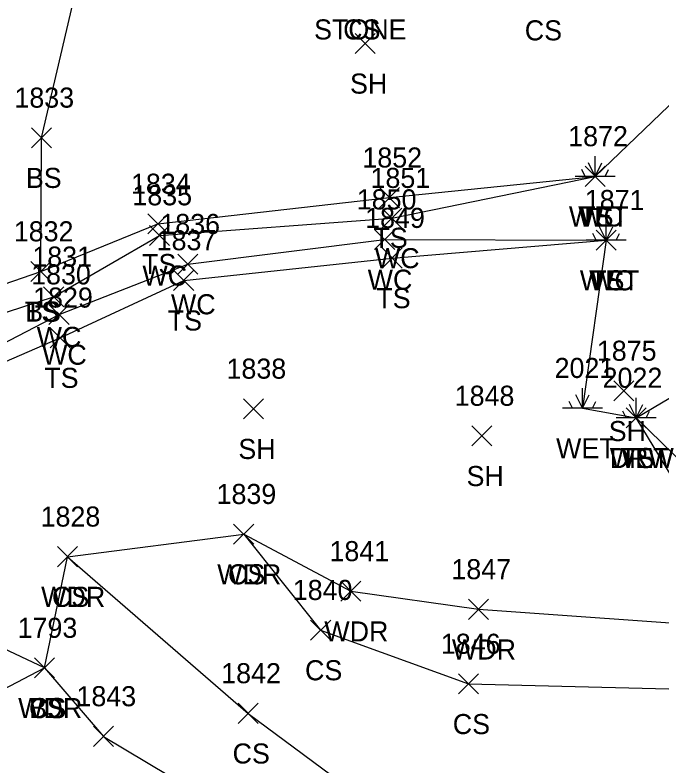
# Model space of a CAD drawing. Extents: x 1512665 to 1513714, y 110636 to 112816.
# Drawn here: x 1512769.8 to 1512834.1, y 110915.7 to 110990.4 of the extents above; entities that cross this region are included whole.
import ezdxf

# ---------------------------------------------------------------- set-up
doc = ezdxf.new("R2010")
doc.units = 0
for name, color, linetype in [('L_A', 7, 'Continuous'), ('L_I', 7, 'Continuous'), ('L_TIC', 7, 'Continuous'), ('LAWA', 7, 'Continuous'), ('LAWE', 7, 'Continuous'), ('LELB', 7, 'Continuous'), ('LWET', 7, 'Continuous'), ('R_A', 7, 'Continuous'), ('R_I', 7, 'Continuous'), ('R_TIC', 7, 'Continuous'), ('RDW', 7, 'Continuous')]:
    doc.layers.add(name, color=color, linetype=linetype)

msp = doc.modelspace()

# ---------------------------------------------------------------- linework, layer by layer
at = {"layer": 'L_TIC'}
for points in [[(1512803.661, 110986.564), (1512805.661, 110988.564)], [(1512805.661, 110986.564), (1512803.661, 110988.564)], [(1512771.399, 110977.169), (1512773.399, 110979.169)], [(1512773.399, 110977.169), (1512771.399, 110979.169)], [(1512826.592, 110973.325), (1512828.592, 110975.325)], [(1512828.592, 110973.325), (1512826.592, 110975.325)], [(1512826.592, 110973.325), (1512828.592, 110975.325)], [(1512828.592, 110973.325), (1512826.592, 110975.325)], [(1512806.078, 110971.203), (1512808.078, 110973.203)], [(1512808.078, 110971.203), (1512806.078, 110973.203)], [(1512806.324, 110969.171), (1512808.324, 110971.171)], [(1512808.324, 110969.171), (1512806.324, 110971.171)], [(1512783.014, 110968.588), (1512785.014, 110970.588)], [(1512785.014, 110968.588), (1512783.014, 110970.588)], [(1512783.154, 110967.439), (1512785.154, 110969.439)], [(1512785.154, 110967.439), (1512783.154, 110969.439)], [(1512805.605, 110967.031), (1512807.605, 110969.031)], [(1512807.605, 110967.031), (1512805.605, 110969.031)], [(1512827.676, 110966.967), (1512829.676, 110968.967)], [(1512829.676, 110966.967), (1512827.676, 110968.967)], [(1512827.676, 110966.967), (1512829.676, 110968.967)], [(1512829.676, 110966.967), (1512827.676, 110968.967)], [(1512785.997, 110964.581), (1512787.997, 110966.581)], [(1512787.997, 110964.581), (1512785.997, 110966.581)], [(1512806.363, 110965.187), (1512808.363, 110967.187)], [(1512808.363, 110965.187), (1512806.363, 110967.187)], [(1512771.336, 110963.849), (1512773.336, 110965.849)], [(1512773.336, 110963.849), (1512771.336, 110965.849)], [(1512771.336, 110963.849), (1512773.336, 110965.849)], [(1512773.336, 110963.849), (1512771.336, 110965.849)], [(1512785.574, 110962.964), (1512787.574, 110964.964)], [(1512787.574, 110962.964), (1512785.574, 110964.964)], [(1512772.614, 110961.333), (1512774.614, 110963.333)], [(1512774.614, 110961.333), (1512772.614, 110963.333)], [(1512773.151, 110959.557), (1512775.151, 110961.557)], [(1512775.151, 110959.557), (1512773.151, 110961.557)], [(1512773.27, 110957.25), (1512775.27, 110959.25)], [(1512775.27, 110957.25), (1512773.27, 110959.25)], [(1512829.448, 110951.951), (1512831.448, 110953.951)], [(1512831.448, 110951.951), (1512829.448, 110953.951)], [(1512792.536, 110950.168), (1512794.536, 110952.168)], [(1512794.536, 110950.168), (1512792.536, 110952.168)], [(1512830.666, 110949.261), (1512832.666, 110951.261)], [(1512832.666, 110949.261), (1512830.666, 110951.261)], [(1512815.28, 110947.469), (1512817.28, 110949.469)], [(1512817.28, 110947.469), (1512815.28, 110949.469)], [(1512791.554, 110937.683), (1512793.554, 110939.683)], [(1512793.554, 110937.683), (1512791.554, 110939.683)], [(1512791.554, 110937.683), (1512793.554, 110939.683)], [(1512793.554, 110937.683), (1512791.554, 110939.683)], [(1512774.007, 110935.434), (1512776.007, 110937.434)], [(1512776.007, 110935.434), (1512774.007, 110937.434)], [(1512774.007, 110935.434), (1512776.007, 110937.434)], [(1512776.007, 110935.434), (1512774.007, 110937.434)], [(1512802.23, 110931.988), (1512804.23, 110933.988)], [(1512804.23, 110931.988), (1512802.23, 110933.988)], [(1512814.948, 110930.191), (1512816.948, 110932.191)], [(1512816.948, 110930.191), (1512814.948, 110932.191)], [(1512799.227, 110928.122), (1512801.227, 110930.122)], [(1512801.227, 110928.122), (1512799.227, 110930.122)], [(1512771.715, 110924.351), (1512773.715, 110926.351)], [(1512773.715, 110924.351), (1512771.715, 110926.351)], [(1512771.715, 110924.351), (1512773.715, 110926.351)], [(1512773.715, 110924.351), (1512771.715, 110926.351)], [(1512771.715, 110924.351), (1512773.715, 110926.351)], [(1512773.715, 110924.351), (1512771.715, 110926.351)], [(1512813.954, 110922.761), (1512815.954, 110924.761)], [(1512815.954, 110922.761), (1512813.954, 110924.761)], [(1512813.954, 110922.761), (1512815.954, 110924.761)], [(1512815.954, 110922.761), (1512813.954, 110924.761)], [(1512792.008, 110919.829), (1512794.008, 110921.829)], [(1512794.008, 110919.829), (1512792.008, 110921.829)], [(1512777.581, 110917.536), (1512779.581, 110919.536)], [(1512779.581, 110917.536), (1512777.581, 110919.536)]]:
    msp.add_lwpolyline(points, dxfattribs=at)
at = {"layer": 'LAWA'}
msp.add_lwpolyline([(1512760.327, 110918.9), (1512772.715, 110925.351), (1512775.007, 110936.434), (1512792.554, 110938.683), (1512803.23, 110932.988), (1512815.948, 110931.191), (1512841.584, 110929.37), (1512844.095, 110932.413), (1512851.809, 110930.104), (1512861.965, 110937.336), (1512864.411, 110940.492), (1512867.897, 110945.243), (1512874.74, 110954.614), (1512875.763, 110966.444), (1512876.134, 110982.426), (1512872.076, 110997.369), (1512855.488, 111002.566), (1512840.685, 111007.355)], dxfattribs=at)
at = {"layer": 'LAWE'}
for points in [[(1512746.764, 110945.419), (1512740.821, 110941.632), (1512736.512, 110940.348), (1512731.136, 110940.569), (1512729.955, 110944.591), (1512735.115, 110946.434), (1512744.855, 110949.263), (1512755.414, 110956.396), (1512773.614, 110962.333), (1512784.154, 110968.439), (1512807.324, 110970.171), (1512827.592, 110974.325)], [(1512746.764, 110945.419), (1512757.856, 110952.087), (1512774.151, 110960.557), (1512786.997, 110965.581), (1512806.605, 110968.031), (1512828.676, 110967.967)]]:
    msp.add_lwpolyline(points, dxfattribs=at)
at = {"layer": 'LELB'}
for points in [[(1512772.715, 110925.351), (1512762.158, 110930.327), (1512751.737, 110933.336), (1512742.777, 110937.317), (1512736.512, 110940.348), (1512735.115, 110946.434), (1512734.831, 110948.182), (1512726.838, 110970.203), (1512728.515, 110982.352), (1512729.638, 111009.802), (1512731.498, 111029.762), (1512731.781, 111051.668)], [(1512772.336, 110964.849), (1512772.399, 110978.169), (1512777.439, 110999.779), (1512776.729, 111007.428), (1512782.279, 111028.359), (1512785.098, 111051.818)], [(1512729.955, 110944.591), (1512734.831, 110948.182), (1512743.342, 110950.503), (1512753.918, 110958.515), (1512772.336, 110964.849), (1512784.014, 110969.588), (1512807.078, 110972.203), (1512827.592, 110974.325)], [(1512742.777, 110937.317), (1512747.507, 110944.423), (1512757.938, 110951.161), (1512774.27, 110958.25), (1512786.574, 110963.964), (1512807.363, 110966.187), (1512828.676, 110967.967)], [(1512844.095, 110932.413), (1512838.189, 110939.553), (1512831.666, 110950.261)], [(1512792.554, 110938.683), (1512800.227, 110929.122), (1512814.954, 110923.761)], [(1512775.007, 110936.434), (1512793.008, 110920.829), (1512810.428, 110907.882)], [(1512772.715, 110925.351), (1512778.581, 110918.536), (1512796.221, 110907.99), (1512810.428, 110907.882), (1512837.589, 110899.205), (1512847.527, 110891.123)], [(1512814.954, 110923.761), (1512842.917, 110923.066), (1512853.188, 110920.094), (1512868.389, 110909.222), (1512891.99, 110892.675)]]:
    msp.add_lwpolyline(points, dxfattribs=at)
at = {"layer": 'LWET'}
for p, q in [((1512827.592, 110974.325), (1512827.592, 110976.325)), ((1512827.592, 110974.325), (1512826.925, 110975.658)), ((1512827.592, 110974.325), (1512828.258, 110975.658)), ((1512826.592, 110974.325), (1512826.258, 110974.991)), ((1512828.592, 110974.325), (1512828.925, 110974.991)), ((1512829.592, 110974.325), (1512825.592, 110974.325)), ((1512828.676, 110967.967), (1512828.676, 110969.967)), ((1512828.676, 110967.967), (1512828.009, 110969.3)), ((1512828.676, 110967.967), (1512829.343, 110969.3)), ((1512830.676, 110967.967), (1512826.676, 110967.967)), ((1512827.676, 110967.967), (1512827.343, 110968.633)), ((1512829.676, 110967.967), (1512830.009, 110968.633)), ((1512826.314, 110951.237), (1512826.314, 110953.237)), ((1512826.314, 110951.237), (1512825.648, 110952.57)), ((1512826.314, 110951.237), (1512826.981, 110952.57)), ((1512831.666, 110950.261), (1512831.666, 110952.261)), ((1512825.314, 110951.237), (1512824.981, 110951.903)), ((1512827.314, 110951.237), (1512827.648, 110951.903)), ((1512831.666, 110950.261), (1512831, 110951.594)), ((1512831.666, 110950.261), (1512832.333, 110951.594)), ((1512828.314, 110951.237), (1512824.314, 110951.237)), ((1512830.666, 110950.261), (1512830.333, 110950.927)), ((1512832.666, 110950.261), (1512833, 110950.927)), ((1512833.666, 110950.261), (1512829.666, 110950.261))]:
    msp.add_line(p, q, dxfattribs=at)
for points in [[(1512827.592, 110974.325), (1512838.974, 110985.231), (1512857.888, 110992.021), (1512872.076, 110997.369), (1512896.468, 110995.837), (1512920.134, 110990.073), (1512933.522, 110995.148), (1512956.567, 110999.31), (1512966.081, 111012.924), (1512978.758, 111015.543)], [(1512828.676, 110967.967), (1512826.314, 110951.237), (1512831.666, 110950.261), (1512846.807, 110959.221), (1512852.714, 110961.858), (1512857.825, 110959.552), (1512867.091, 110954.959), (1512874.74, 110954.614), (1512893.574, 110955.661), (1512912.432, 110939.219), (1512933.394, 110947.269), (1512941.465, 110952.585), (1512958.813, 110964.455), (1512973.513, 110967.07), (1512985.654, 110971.062)]]:
    msp.add_lwpolyline(points, dxfattribs=at)
at = {"layer": 'R_TIC'}
for points in [[(1512830.666, 110949.261), (1512832.666, 110951.261)], [(1512832.666, 110949.261), (1512830.666, 110951.261)]]:
    msp.add_lwpolyline(points, dxfattribs=at)
at = {"layer": 'RDW'}
msp.add_lwpolyline([(1512831.666, 110950.261), (1512839.34, 110942.793), (1512851.809, 110930.104), (1512872.871, 110913.575), (1512891.99, 110892.675), (1512913.156, 110874.506), (1512928.573, 110854.542), (1512938.494, 110838.55), (1512948.315, 110825.655), (1512947.325, 110821.384), (1512945.804, 110819.115), (1512944.462, 110817.212)], dxfattribs=at)

# ---------------------------------------------------------------- texts
at = {"layer": 'L_A'}
for s, p in [('STONE', (1512799.571, 110987.959)), ('CS', (1512802.469, 110987.959)), ('CS', (1512820.569, 110987.869)), ('SH', (1512803.15, 110982.564)), ('BS', (1512770.84, 110973.169)), ('WET', (1512824.97, 110969.325)), ('WC', (1512825.899, 110969.325)), ('TS', (1512826.001, 110969.325)), ('TS', (1512805.487, 110967.203)), ('TS', (1512782.423, 110964.588)), ('WC', (1512805.631, 110965.171)), ('WC', (1512782.461, 110963.439)), ('WC', (1512804.912, 110963.031)), ('WET', (1512826.054, 110962.967)), ('WC', (1512826.983, 110962.967)), ('TS', (1512827.086, 110962.967)), ('TS', (1512805.773, 110961.187)), ('WC', (1512785.304, 110960.581)), ('TS', (1512770.745, 110959.849)), ('BS', (1512770.777, 110959.849)), ('TS', (1512784.983, 110958.964)), ('WC', (1512771.921, 110957.333)), ('WC', (1512772.458, 110955.557)), ('TS', (1512772.679, 110953.25)), ('SH', (1512828.936, 110947.951)), ('SH', (1512792.025, 110946.168)), ('WET', (1512823.692, 110946.237)), ('WET', (1512829.044, 110945.261)), ('TS', (1512830.076, 110945.261)), ('SH', (1512814.768, 110943.469)), ('WDR', (1512789.916, 110933.683)), ('CS', (1512790.995, 110933.683)), ('WDR', (1512772.369, 110931.434)), ('CS', (1512773.448, 110931.434)), ('WDR', (1512800.592, 110927.988)), ('WDR', (1512813.31, 110926.191)), ('CS', (1512798.668, 110924.122)), ('CS', (1512771.156, 110920.351)), ('BS', (1512771.156, 110920.351)), ('WDR', (1512770.078, 110920.351)), ('CS', (1512813.395, 110918.761)), ('CS', (1512813.395, 110918.761)), ('CS', (1512791.449, 110915.829))]:
    msp.add_text(s, height=2, dxfattribs=at).set_placement(p)
at = {"layer": 'L_I'}
for s, p in [('1833', (1512769.706, 110981.169)), ('1872', (1512824.899, 110977.325)), ('1872', (1512824.899, 110977.325)), ('1872', (1512824.899, 110977.325)), ('1852', (1512804.385, 110975.203)), ('1851', (1512805.198, 110973.171)), ('1834', (1512781.321, 110972.588)), ('1835', (1512781.461, 110971.439)), ('1850', (1512803.826, 110971.031)), ('1871', (1512826.55, 110970.967)), ('1871', (1512826.55, 110970.967)), ('1871', (1512826.55, 110970.967)), ('1849', (1512804.663, 110969.187)), ('1836', (1512784.249, 110968.581)), ('1832', (1512769.643, 110967.849)), ('1832', (1512769.643, 110967.849)), ('1837', (1512783.881, 110966.964)), ('1831', (1512771.488, 110965.333)), ('1830', (1512771.371, 110963.557)), ('1829', (1512771.569, 110961.25)), ('1875', (1512827.755, 110955.951)), ('1838', (1512790.844, 110954.168)), ('2021', (1512823.543, 110954.237)), ('2022', (1512828.328, 110953.261)), ('2022', (1512828.328, 110953.261)), ('1848', (1512813.587, 110951.469)), ('1839', (1512789.853, 110941.683)), ('1839', (1512789.853, 110941.683)), ('1828', (1512772.314, 110939.434)), ('1828', (1512772.314, 110939.434)), ('1841', (1512801.104, 110935.988)), ('1847', (1512813.255, 110934.191)), ('1840', (1512797.447, 110932.122)), ('1793', (1512770.023, 110928.351)), ('1793', (1512770.023, 110928.351)), ('1793', (1512770.023, 110928.351)), ('1846', (1512812.206, 110926.761)), ('1846', (1512812.206, 110926.761)), ('1842', (1512790.315, 110923.829)), ('1843', (1512775.889, 110921.536))]:
    msp.add_text(s, height=2, dxfattribs=at).set_placement(p)
at = {"layer": 'R_A'}
msp.add_text('DRW', height=2, dxfattribs=at).set_placement((1512829.036, 110945.261))
at = {"layer": 'R_I'}
msp.add_text('2022', height=2, dxfattribs=at).set_placement((1512828.328, 110953.261))

doc.saveas('drawing.dxf')
